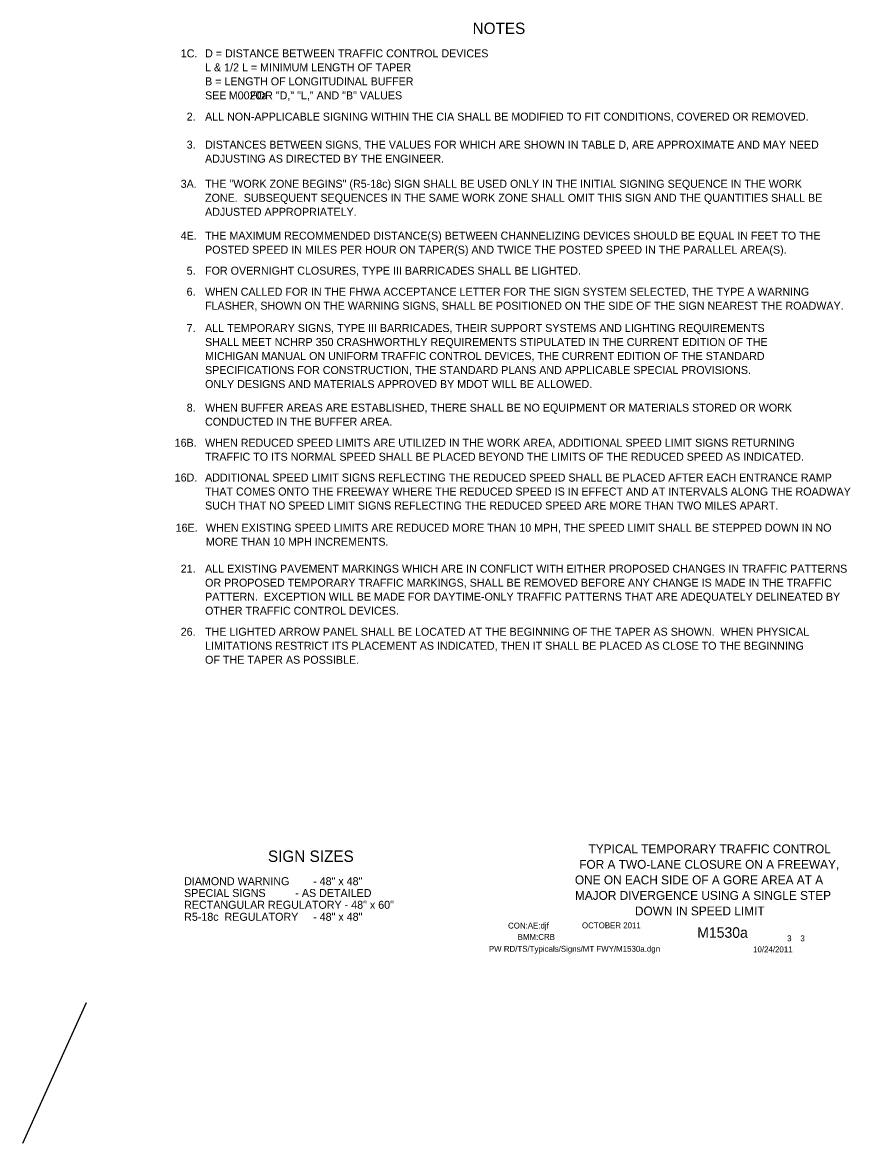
# Model space of a CAD drawing. Extents: x 16452 to 19508, y 5713 to 7079.
# Drawn here: x 18639 to 19508, y 5732 to 6909 of the extents above; entities that cross this region are included whole.
import ezdxf

# ---------------------------------------------------------------- set-up
doc = ezdxf.new("R2010")
doc.units = 0
for name, color, linetype in [('BORDER', 7, 'Continuous'), ('BORDER_SIGNAL_WO', 7, 'Continuous'), ('TYPICAL_TEXT_DIMEN_PR', 7, 'Continuous')]:
    doc.layers.add(name, color=color, linetype=linetype)

msp = doc.modelspace()

# ---------------------------------------------------------------- linework, layer by layer
at = {"layer": 'TYPICAL_TEXT_DIMEN_PR'}
msp.add_line((18705.8, 5880), (18639, 5732.4), dxfattribs=at)

# ---------------------------------------------------------------- texts
at = {"layer": 'BORDER'}
for s, p in [('TYPICAL TEMPORARY TRAFFIC CONTROL', (19233.2, 6037.1)), ('FOR A TWO-LANE CLOSURE ON A FREEWAY,', (19223.4, 6020.8)), ('ONE ON EACH SIDE OF A GORE AREA AT A ', (19218.9, 6004.5)), ('MAJOR DIVERGENCE USING A SINGLE STEP ', (19218.9, 5988.2)), ('DOWN IN SPEED LIMIT', (19281.9, 5971.9))]:
    msp.add_text(s, height=9.3, dxfattribs=at).set_placement(p)
at = {"layer": 'BORDER_SIGNAL_WO'}
for s, height, p in [('CON:AE:djf  ', 6.2, (19148.7, 5958.1)), ('    OCTOBER 2011    ', 6.2, (19217.1, 5958.3)), ('    M1530a   ', 11, (19330.9, 5948.4)), ('BMM:CRB   ', 6.2, (19158.8, 5946.2)), (' 3    3 ', 6.2, (19439.4, 5944.7)), ('PW RD/TS/Typicals/Signs/MT FWY/M1530a.dgn      ', 6.2, (19128.6, 5933.7)), ('10/24/2011    ', 6.2, (19405.9, 5933.1))]:
    msp.add_text(s, height=height, dxfattribs=at).set_placement(p)
at = {"layer": 'TYPICAL_TEXT_DIMEN_PR'}
for s, height, p in [('NOTES', 12, (19111.5, 6897)), ('1C.', 8.4, (18805.2, 6872.5)), ('D = DISTANCE BETWEEN TRAFFIC CONTROL DEVICES', 8.4, (18830.7, 6872.5)), ('L & 1/2 L = MINIMUM LENGTH OF TAPER', 8.4, (18830.7, 6857.8)), ('B = LENGTH OF LONGITUDINAL BUFFER', 8.4, (18830.7, 6843.1)), ('SEE        FOR "D," "L," AND "B" VALUES', 8.4, (18830.7, 6828.4)), ('M0020a', 8.4, (18855.6, 6828.4)), ('2.', 8.4, (18811.4, 6806.1)), ('ALL NON-APPLICABLE SIGNING WITHIN THE CIA SHALL BE MODIFIED TO FIT CONDITIONS, COVERED OR REMOVED.', 8.4, (18830.7, 6806.1)), ('3.', 8.4, (18811.4, 6776.7)), ('DISTANCES BETWEEN SIGNS, THE VALUES FOR WHICH ARE SHOWN IN TABLE D, ARE APPROXIMATE AND MAY NEED', 8.4, (18830.7, 6776.7)), ('ADJUSTING AS DIRECTED BY THE ENGINEER.', 8.4, (18830.7, 6762)), ('3A.', 8.4, (18805.1, 6735.6)), ('THE "WORK ZONE BEGINS" (R5-18c) SIGN SHALL BE USED ONLY IN THE INITIAL SIGNING SEQUENCE IN THE WORK', 8.4, (18830.7, 6735.6)), ('ZONE.  SUBSEQUENT SEQUENCES IN THE SAME WORK ZONE SHALL OMIT THIS SIGN AND THE QUANTITIES SHALL BE', 8.4, (18830.7, 6720.9)), ('ADJUSTED APPROPRIATELY.', 8.4, (18830.7, 6706.2)), ('4E.', 8.4, (18805.1, 6681.2)), ('THE MAXIMUM RECOMMENDED DISTANCE(S) BETWEEN CHANNELIZING DEVICES SHOULD BE EQUAL IN FEET TO THE', 8.4, (18830.7, 6681.2)), ('POSTED SPEED IN MILES PER HOUR ON TAPER(S) AND TWICE THE POSTED SPEED IN THE PARALLEL AREA(S).', 8.4, (18830.7, 6666.4)), ('5.', 8.4, (18811.4, 6644.4)), ('FOR OVERNIGHT CLOSURES, TYPE III BARRICADES SHALL BE LIGHTED. ', 8.4, (18830.7, 6644.4)), ('6.', 8.4, (18811.3, 6622.3)), ('WHEN CALLED FOR IN THE FHWA ACCEPTANCE LETTER FOR THE SIGN SYSTEM SELECTED, THE TYPE A WARNING ', 8.4, (18830.7, 6622.3)), ('FLASHER, SHOWN ON THE WARNING SIGNS, SHALL BE POSITIONED ON THE SIDE OF THE SIGN NEAREST THE ROADWAY.', 8.4, (18830.7, 6607.6)), ('7.', 8.4, (18811.3, 6584.2)), ('ALL TEMPORARY SIGNS, TYPE III BARRICADES, THEIR SUPPORT SYSTEMS AND LIGHTING REQUIREMENTS', 8.4, (18830.7, 6584.2)), ('SHALL MEET NCHRP 350 CRASHWORTHLY REQUIREMENTS STIPULATED IN THE CURRENT EDITION OF THE', 8.4, (18830.7, 6569.5)), ('MICHIGAN MANUAL ON UNIFORM TRAFFIC CONTROL DEVICES, THE CURRENT EDITION OF THE STANDARD', 8.4, (18830.7, 6554.8)), ('SPECIFICATIONS FOR CONSTRUCTION, THE STANDARD PLANS AND APPLICABLE SPECIAL PROVISIONS.', 8.4, (18830.7, 6540.1)), ('ONLY DESIGNS AND MATERIALS APPROVED BY MDOT WILL BE ALLOWED.', 8.4, (18830.7, 6525.4)), ('8.', 8.4, (18811.4, 6500.6)), ('WHEN BUFFER AREAS ARE ESTABLISHED, THERE SHALL BE NO EQUIPMENT OR MATERIALS STORED OR WORK     ', 8.4, (18830.7, 6500.6)), ('CONDUCTED IN THE BUFFER AREA.', 8.4, (18830.7, 6485.9)), ('16B.', 8.4, (18798.8, 6463.8)), ('WHEN REDUCED SPEED LIMITS ARE UTILIZED IN THE WORK AREA, ADDITIONAL SPEED LIMIT SIGNS RETURNING', 8.4, (18830.7, 6463.8)), ('TRAFFIC TO ITS NORMAL SPEED SHALL BE PLACED BEYOND THE LIMITS OF THE REDUCED SPEED AS INDICATED.', 8.4, (18830.7, 6449.1)), ('16D.', 8.4, (18798.8, 6427.3)), ('ADDITIONAL SPEED LIMIT SIGNS REFLECTING THE REDUCED SPEED SHALL BE PLACED AFTER EACH ENTRANCE RAMP', 8.4, (18830.7, 6427.3)), ('THAT COMES ONTO THE FREEWAY WHERE THE REDUCED SPEED IS IN EFFECT AND AT INTERVALS ALONG THE ROADWAY', 8.4, (18830.7, 6412.6)), ('SUCH THAT NO SPEED LIMIT SIGNS REFLECTING THE REDUCED SPEED ARE MORE THAN TWO MILES APART.', 8.4, (18830.7, 6397.9)), ('16E.', 8.4, (18799.8, 6374.6)), ('WHEN EXISTING SPEED LIMITS ARE REDUCED MORE THAN 10 MPH, THE SPEED LIMIT SHALL BE STEPPED DOWN IN NO', 8.4, (18831.6, 6374.6)), ('MORE THAN 10 MPH INCREMENTS.', 8.4, (18831.6, 6359.9)), ('21.', 8.4, (18805.1, 6331.6)), ('ALL EXISTING PAVEMENT MARKINGS WHICH ARE IN CONFLICT WITH EITHER PROPOSED CHANGES IN TRAFFIC PATTERNS', 8.4, (18830.7, 6331.6)), ('OR PROPOSED TEMPORARY TRAFFIC MARKINGS, SHALL BE REMOVED BEFORE ANY CHANGE IS MADE IN THE TRAFFIC', 8.4, (18830.7, 6316.9)), ('PATTERN.  EXCEPTION WILL BE MADE FOR DAYTIME-ONLY TRAFFIC PATTERNS THAT ARE ADEQUATELY DELINEATED BY', 8.4, (18830.7, 6302.2)), ('OTHER TRAFFIC CONTROL DEVICES.', 8.4, (18830.7, 6287.5)), ('26.', 8.4, (18805.1, 6265.4)), ('THE LIGHTED ARROW PANEL SHALL BE LOCATED AT THE BEGINNING OF THE TAPER AS SHOWN.  WHEN PHYSICAL', 8.4, (18830.7, 6265.4)), ('LIMITATIONS RESTRICT ITS PLACEMENT AS INDICATED, THEN IT SHALL BE PLACED AS CLOSE TO THE BEGINNING', 8.4, (18830.7, 6250.7)), ('OF THE TAPER AS POSSIBLE.', 8.4, (18830.7, 6236)), ('SIGN SIZES', 12, (18896.7, 6028)), ('DIAMOND WARNING        - 48" x 48"', 8.4, (18808.7, 6003.6)), ('SPECIAL SIGNS          - AS DETAILED', 8.4, (18808.7, 5991.2)), ('RECTANGULAR REGULATORY - 48" x 60"', 8.4, (18808.7, 5978.8)), ('R5-18c  REGULATORY     - 48" x 48"', 8.4, (18808.7, 5966.2))]:
    msp.add_text(s, height=height, dxfattribs=at).set_placement(p)

doc.saveas('drawing.dxf')
